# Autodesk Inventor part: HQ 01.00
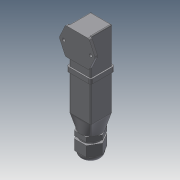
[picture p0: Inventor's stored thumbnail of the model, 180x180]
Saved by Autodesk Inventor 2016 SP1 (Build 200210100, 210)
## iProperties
Created: 2017-05
Part Number: HQ 01.00
Checked By: Сидоров ИА
Engr Approved By: Баев БГ
Material: Типовые
Document SubType Name: Modeling
Mfg Approved By: Босов АА
Designer: t1
Engineer: Иванов НИ
Authority: Петров ПП
Mass: 69.0903 g
Surface Area: 142.504 cm^2
Volume: 69.0903 cm^3
Density: 1 g/cm^3
Appearance: По умолчанию
Company: Проектная группа
Author: t1
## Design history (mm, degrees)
sketch "Эскиз2"
  geometry: L1 (12, -12)-(-12, -12); L2 (-12, -12)-(-12, 12); L3 (-12, 12)-(12, 12); L4 (12, 12)-(12, -12); L5 (12, -12)-(-12, 12); L6 (-12, -12)-(12, 12); 1 further point
  constraints: 12 end point, 2 midpoint, 2 parallel, 2 perpendicular, 1 horizontal
  dimensions: "d10" = 24 distance of L2.end L3.end
extrude "Выдавливание1" new body sketch "Эскиз2" distance "d11" = 40; taper "d12" = 0 deg
sketch "Эскиз3"
  geometry: L1 (0, 40)-(24, 40) reference; L2 (12, 43.335)-(12, -3.58) reference; L3 (-8, 10)-(32, 10); L4 (32, 10)-(32, 40); L5 (32, 40)-(-8, 40); L6 (-8, 40)-(-8, 10); L7 (-8, 10)-(32, 40); L8 (32, 10)-(-8, 40); L9 (33.37, 25)-(-12.194, 25); L10 (-8, 25)-(-1.141, 40); L11 (-8, 25)-(-1.141, 10); L12 (32, 25)-(25.141, 40); L13 (32, 25)-(25.141, 10); C1 r 1.65 at (-3, 25); C2 r 1.65 at (27, 25); 4 further points
  constraints: 24 end point, 8 point on line, 4 midpoint, 4 parallel, 2 centre point, 2 coincident, 2 equal length, 2 horizontal, 2 vertical, 1 collinear, 1 perpendicular, 1 symmetric about line, 1 other
  dimensions: "d13" = 40 distance of L4.end L5.end; "d14" = 30 distance of L3.end L4.end; "d15" = 30 diameter of C1.centre L2; "d16" = 3.3 diameter of C1
extrude "Выдавливание2" join sketch "Эскиз3" distance "d17" = 3; taper "d18" = 0 deg
fillet "Сопряжение1" dims "d19" = 2
hole "Отверстие1" sketch "Эскиз3" diameter "d20" = 3.3; stored, may be unused: countersink angle "d24" = 90 deg, drill point angle "d26" = 118 deg; dims "d21" = 6, "d22" = 4, "d23" = 2, "d25" = 8
fillet "Сопряжение2" dims "d27" = 1
fillet "Сопряжение3" dims "d28" = 1
sketch "Эскиз4"
  geometry: L1 (-11, -12)-(11, -12) reference; L2 (12, -11)-(12, 11) reference; L3 (11, 12)-(-11, 12) reference; L4 (-12, 11)-(-12, -11) reference; L5 (-11, 13.5)-(11, 13.5); L6 (13.5, 11)-(13.5, -11); L7 (11, -13.5)-(-11, -13.5); L8 (-13.5, -11)-(-13.5, 11); A1 r 1 centre (-11, -11) between (-12, -11) and (-11, -12) reference; A2 r 1 centre (11, -11) between (11, -12) and (12, -11) reference; A3 r 1 centre (11, 11) between (12, 11) and (11, 12) reference; A4 r 1 centre (-11, 11) between (-11, 12) and (-12, 11) reference; A5 r 2.5 centre (11, 11) between (13.5, 11) and (11, 13.5); A6 r 2.5 centre (11, -11) between (11, -13.5) and (13.5, -11); A7 r 2.5 centre (-11, -11) between (-13.5, -11) and (-11, -13.5); A8 r 2.5 centre (-11, 11) between (-11, 13.5) and (-13.5, 11); 1 further point
  constraints: 8 end point, 8 point on circle, 4 centre point, 7 other
  dimensions: "d29" = 1.5 distance between parallel lines of L5 L3
extrude "Выдавливание3" join sketch "Эскиз4" distance "d30" = 5; taper "d31" = 0 deg
sketch "Эскиз5"
  geometry: L1 (11, 13.5)-(-11, 13.5) reference; L2 (-13.5, 11)-(-13.5, -11) reference; L3 (-11, -13.5)-(11, -13.5) reference; L4 (13.5, -11)-(13.5, 11) reference; L5 (-11, 12)-(11, 12); L6 (12, 11)-(12, -11); L7 (11, -12)-(-11, -12); L8 (-12, -11)-(-12, 11); A1 r 2.5 centre (-11, 11) between (-11, 13.5) and (-13.5, 11) reference; A2 r 2.5 centre (-11, -11) between (-13.5, -11) and (-11, -13.5) reference; A3 r 2.5 centre (11, -11) between (11, -13.5) and (13.5, -11) reference; A4 r 2.5 centre (11, 11) between (13.5, 11) and (11, 13.5) reference; A5 r 1 centre (11, 11) between (12, 11) and (11, 12); A6 r 1 centre (11, -11) between (11, -12) and (12, -11); A7 r 1 centre (-11, -11) between (-12, -11) and (-11, -12); A8 r 1 centre (-11, 11) between (-11, 12) and (-12, 11); 1 further point
  constraints: 8 end point, 8 point on circle, 4 centre point, 7 other
  dimensions: "d32" = 1.5 distance between parallel lines of L1 L5
extrude "Выдавливание4" join sketch "Эскиз5" distance "d33" = 40; taper "d34" = 0 deg
node "РабПлоскость1"
node "РабПлоскость2"
sketch "Эскиз6"
  geometry: L1 (11, 12)-(-11, 12) reference; L2 (-12, 11)-(-12, -11) reference; L3 (-11, -12)-(11, -12) reference; L4 (12, -11)-(12, 11) reference; A1 r 1 centre (-11, 11) between (-11, 12) and (-12, 11) reference; A2 r 1 centre (-11, -11) between (-12, -11) and (-11, -12) reference; A3 r 1 centre (11, -11) between (11, -12) and (12, -11) reference; A4 r 1 centre (11, 11) between (12, 11) and (11, 12) reference; 1 further point
  node "Спроецированная петля1"
sketch "Эскиз7"
  geometry: C1 r 11.5 at (0, 0); 1 further point
  constraints: 1 centre point, 1 coincident
  dimensions: "d37" = 23 diameter of C1
feature "Лофт1" sketch "Эскиз7" dims "d38" = 0, "d39" = 90 deg, "d40" = 0, "d41" = 90 deg
  node "Ребра1"
sketch "Эскиз8"
  geometry: L1 (6.64, 11.5)-(13.279, 0); L2 (13.279, 0)-(6.64, -11.5); L3 (6.64, -11.5)-(-6.64, -11.5); L4 (-6.64, -11.5)-(-13.279, 0); L5 (-13.279, 0)-(-6.64, 11.5); L6 (-6.64, 11.5)-(6.64, 11.5); A1 r 11.5 centre (0, 0) between (8.477, 7.771) and (7.771, 8.477) reference; 1 further point
  constraints: 12 end point, 1 coincident, 1 horizontal, 13 other
  dimensions: "d42" = 23 distance between parallel lines of L3 L6
extrude "Выдавливание5" join sketch "Эскиз8" distance "d43" = 5; taper "d44" = 0 deg
sketch "Эскиз9"
  geometry: C1 r 10 at (0, 0); 1 further point
  constraints: 1 centre point, 1 coincident
  dimensions: "d45" = 20 diameter of C1
extrude "Выдавливание6" join sketch "Эскиз9" distance "d46" = 3; taper "d47" = 0 deg
sketch "Эскиз10"
  geometry: L1 (-6.652, 11.521)-(6.652, 11.521); L2 (6.652, 11.521)-(13.304, 0); L3 (13.304, 0)-(6.652, -11.521); L4 (6.652, -11.521)-(-6.652, -11.521); L5 (-6.652, -11.521)-(-13.304, 0); L6 (-13.304, 0)-(-6.652, 11.521); C1 r 10 at (0, 0) reference; 1 further point
  constraints: 12 end point, 1 coincident, 1 horizontal, 13 other
extrude "Выдавливание7" join sketch "Эскиз10" distance "d48" = 12; taper "d49" = 0 deg
node "РабПлоскость3"
sketch "Эскиз11"
  geometry: L1 (12, -0.557)-(10.964, -0.557); L2 (12, 6.652)-(12, 0) reference; L3 (12, 19.955)-(12, 6.652) reference; L4 (12, 26.607)-(12, 19.955) reference; L5 (12, 13.304)-(25.012, 13.304); L6 (12, -0.557)-(12, 3.995); L7 (10.964, -0.557)-(12, 3.995); 1 further point
  constraints: 8 end point, 1 horizontal, 1 midpoint, 1 point on line
revolve "Вращение1" sketch "Эскиз11" stored, may be unused: angle "d50" = 90 deg
sketch "Эскиз12"
  geometry: C1 r 11.37 at (0, 0); 1 further point
  constraints: 1 centre point, 1 coincident
extrude "Выдавливание8" join sketch "Эскиз12" distance "d51" = 6; taper "d53" = 0 deg; dims "d52" = 3, "d54" = 0
fillet "Сопряжение4" dims "d55" = 5
sketch "Эскиз13"
  geometry: C1 r 6.37 at (0, 0) reference; C2 r 6 at (0, 0)
  constraints: 1 centre point, 1 coincident
  dimensions: "d56" = 12 diameter of C2
extrude "Выдавливание9" cut sketch "Эскиз13" distance "d57" = 15; taper "d58" = 0 deg
node "Твердое тело2"
other parameters: "d35" = 0, "d36" = 15
